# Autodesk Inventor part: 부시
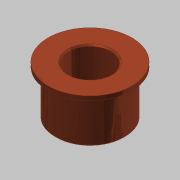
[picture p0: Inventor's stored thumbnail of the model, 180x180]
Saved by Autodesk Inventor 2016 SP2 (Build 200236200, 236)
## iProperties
Created: 2015-10
Part Number: 부시
Document SubType Name: Modeling
Designer: mdu
Density: 7.86 g/cm^3
Material: 강철, 연강
Mass: 364.706 g
Surface Area: 129.307 cm^2
Volume: 46.4003 cm^3
Appearance: 구리 - 새틴
Author: mdu
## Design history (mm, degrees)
sketch "스케치1"
  geometry: C1 r 31 at (0, 0) reference; C2 r 25 at (0, 0) reference; C3 r 30 at (0, 0) reference; 1 further point
  node "참조1"
  node "참조2"
  node "참조4"
extrude "돌출1" new body sketch "스케치1" distance "d0" = 3; taper "d1" = 0 deg
extrude "돌출2" join sketch "스케치1" distance "d2" = 35; taper "d3" = 0 deg
chamfer "모따기1" distance "d6" = 1; stored, may be unused: second distance "d7" = 2, angle "d8" = 45 deg
sketch "스케치3"
  geometry: C1 r 15 at (0, 0); 1 further point
  constraints: 1 centre point, 1 coincident
  dimensions: "d13" = 30 diameter of C1
extrude "돌출4" cut sketch "스케치3" stored distance "d14" = 10; taper "d15" = 0 deg
chamfer "모따기3" distance "d16" = 1; stored, may be unused: second distance "d17" = 2, angle "d18" = 45 deg
node "솔리드1"
